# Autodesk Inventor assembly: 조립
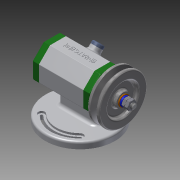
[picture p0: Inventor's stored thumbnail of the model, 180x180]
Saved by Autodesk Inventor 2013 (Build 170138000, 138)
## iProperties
Created: 2017-04
Part Number: 조립
Document SubType Name: Assembly
Designer: Administrator
Author: Administrator
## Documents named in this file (14)
- C:\Users\Administrator\Desktop\470608V1005\조립.iam
- C:\Users\Administrator\Desktop\470608V1005\본체.ipt
- C:\Users\Administrator\Desktop\470608V1005\V벨트풀리.ipt
- C:\Users\Administrator\Desktop\470608V1005\고무캡.ipt
- C:\Users\Administrator\Desktop\470608V1005\너트 M 8.ipt
- C:\Users\Administrator\Desktop\470608V1005\뒤커버.ipt
- C:\Users\Administrator\Desktop\470608V1005\베어링 15 x 32 x 9.ipt
- C:\Users\Administrator\Desktop\470608V1005\볼트 M4 x 12.ipt
- C:\Users\Administrator\Desktop\470608V1005\스프링와셔 8.ipt
- C:\Users\Administrator\Desktop\470608V1005\앞커버.ipt
- C:\Users\Administrator\Desktop\470608V1005\오일 실 15 25 7.ipt
- C:\Users\Administrator\Desktop\470608V1005\와셔 8x17.ipt
- C:\Users\Administrator\Desktop\470608V1005\축.ipt
- C:\Users\Administrator\Desktop\470608V1005\키 3 x 3 x 12.ipt
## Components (2 placed, 2 different names)
1. V벨트풀리:1
2. 고무캡:1
